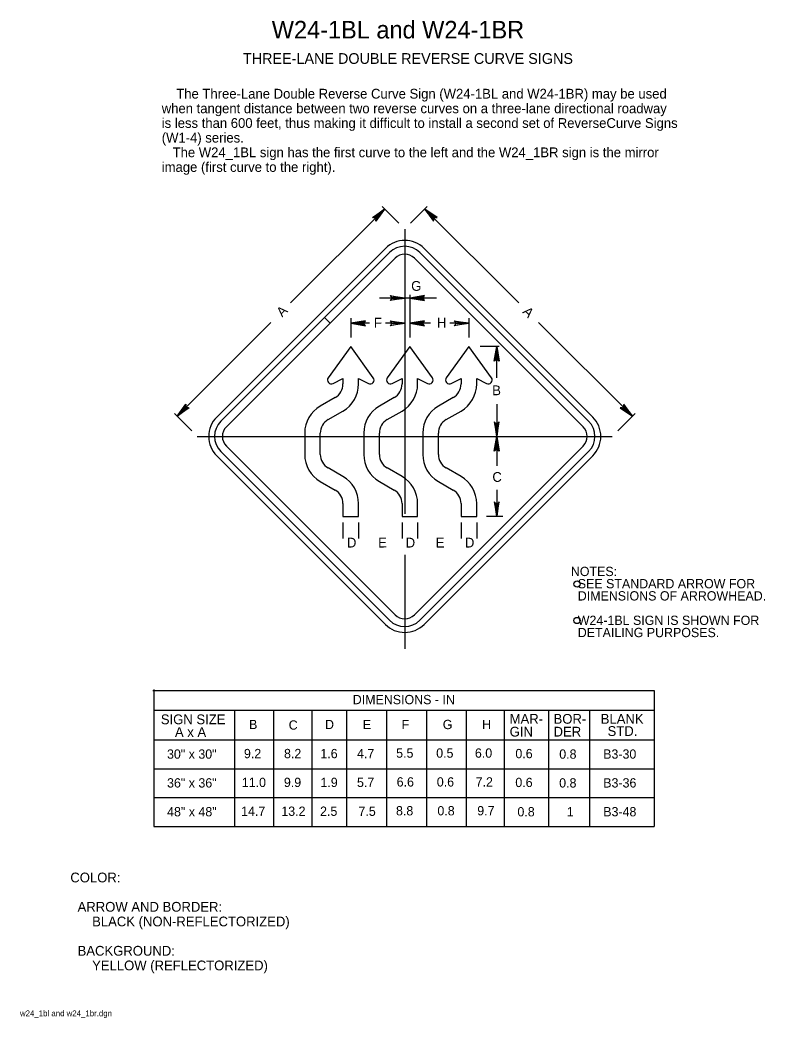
# Model space of a CAD drawing. Extents: x 0.013 to 0.203, y 0.004 to 0.259.
import ezdxf

# ---------------------------------------------------------------- set-up
doc = ezdxf.new("R2010")
doc.units = 0
for name, color, linetype in [('1', 7, 'Continuous'), ('2', 7, 'Continuous'), ('3', 7, 'Continuous')]:
    doc.layers.add(name, color=color, linetype=linetype)

# ---------------------------------------------------------------- blocks, each defined once
blk = doc.blocks.new('RARROW')
at = {"layer": '3'}
for p, q in [((-2.156, 0.28500000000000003), (-2.2665, 0.384625)), ((-2.2665, 0.384625), (0, 0)), ((0, 0), (-2.2665, -0.379125)), ((-2.156, 0.28500000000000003), (-2.075625, 0.12075)), ((0, 0), (-2.156, 0.28500000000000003)), ((-2.14975, -0.2705), (0, 0)), ((-2.075625, 0.12075), (0, 0)), ((0, 0), (-2.074, -0.108)), ((-2.2665, -0.379125), (-2.14975, -0.2705)), ((-2.074, -0.108), (-2.14975, -0.2705))]:
    blk.add_line(p, q, dxfattribs=at)

msp = doc.modelspace()

# ---------------------------------------------------------------- linework, layer by layer
at = {"layer": '1'}
for p, q in [((0.11101043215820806, 0.20572876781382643), (0.11101043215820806, 0.13292717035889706)), ((0.10606068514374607, 0.20078447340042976), (0.06292717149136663, 0.1576509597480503)), ((0.0905074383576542, 0.18310990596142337), (0.10712134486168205, 0.19972381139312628)), ((0.11489951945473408, 0.19972381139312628), (0.15803303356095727, 0.1565902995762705)), ((0.1590936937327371, 0.15765095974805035), (0.1159601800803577, 0.2007844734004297)), ((0.14141602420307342, 0.17532862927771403), (0.1159601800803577, 0.2007844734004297)), ((0.10853555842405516, 0.1983095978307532), (0.0919216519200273, 0.18169569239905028)), ((0.15661881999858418, 0.1551760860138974), (0.11348530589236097, 0.1983095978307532)), ((0.11231043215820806, 0.18893882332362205), (0.11231043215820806, 0.17803722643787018)), ((0.06398783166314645, 0.1565902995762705), (0.0905074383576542, 0.18310990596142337)), ((0.0919216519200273, 0.18169569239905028), (0.06540204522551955, 0.1551760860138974)), ((0.0905074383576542, 0.18310990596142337), (0.0919216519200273, 0.18169569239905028)), ((0.0919216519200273, 0.18169569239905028), (0.0905074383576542, 0.18310990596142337)), ((0.09721043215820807, 0.18292414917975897), (0.09721043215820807, 0.17803722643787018)), ((0.12741043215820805, 0.18292414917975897), (0.12741043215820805, 0.17803722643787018)), ((0.09721043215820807, 0.17570121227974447), (0.09144403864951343, 0.16770795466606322)), ((0.10297682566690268, 0.16770795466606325), (0.09721043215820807, 0.17570121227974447)), ((0.11231043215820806, 0.17570121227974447), (0.10654403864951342, 0.16770795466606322)), ((0.11807682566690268, 0.16770795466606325), (0.11231043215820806, 0.17570121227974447)), ((0.12741043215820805, 0.17570121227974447), (0.12164403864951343, 0.16770795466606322)), ((0.1331768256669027, 0.16770795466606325), (0.12741043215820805, 0.17570121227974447)), ((0.1345331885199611, 0.16766111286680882), (0.1345331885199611, 0.17570121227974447)), ((0.09270945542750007, 0.16623211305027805), (0.09521043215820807, 0.16750795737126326)), ((0.09521043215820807, 0.16750795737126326), (0.09521043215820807, 0.1661232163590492)), ((0.09921043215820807, 0.1661232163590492), (0.09921043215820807, 0.16750795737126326)), ((0.09921043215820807, 0.16750795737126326), (0.10171140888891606, 0.16623211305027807)), ((0.10780945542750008, 0.16623211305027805), (0.11031043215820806, 0.16750795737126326)), ((0.11031043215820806, 0.16750795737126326), (0.11031043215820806, 0.1661232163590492)), ((0.11431043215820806, 0.1661232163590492), (0.11431043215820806, 0.16750795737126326)), ((0.11431043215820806, 0.16750795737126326), (0.11681140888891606, 0.16623211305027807)), ((0.12290945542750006, 0.16623211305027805), (0.12541043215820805, 0.16750795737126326)), ((0.12541043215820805, 0.16750795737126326), (0.12541043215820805, 0.1661232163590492)), ((0.12941043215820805, 0.1661232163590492), (0.12941043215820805, 0.16750795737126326)), ((0.12941043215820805, 0.16750795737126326), (0.13191140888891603, 0.16623211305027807)), ((0.09321043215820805, 0.16265911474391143), (0.08942614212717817, 0.16047425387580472)), ((0.10831043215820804, 0.16265911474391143), (0.10452614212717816, 0.16047425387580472)), ((0.12341043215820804, 0.16265911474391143), (0.11962614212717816, 0.16047425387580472)), ((0.1345331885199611, 0.16097138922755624), (0.1345331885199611, 0.15270121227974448)), ((0.09142614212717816, 0.15701015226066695), (0.09521043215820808, 0.1591950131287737)), ((0.10652614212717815, 0.15701015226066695), (0.11031043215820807, 0.1591950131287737)), ((0.12162614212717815, 0.15701015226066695), (0.12541043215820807, 0.1591950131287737)), ((0.06229525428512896, 0.15700020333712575), (0.06229525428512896, 0.15700020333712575)), ((0.08542614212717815, 0.15354605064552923), (0.08542614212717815, 0.14809720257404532)), ((0.08942614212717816, 0.14809720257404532), (0.08942614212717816, 0.1535460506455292)), ((0.10052614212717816, 0.15354605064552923), (0.10052614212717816, 0.14809720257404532)), ((0.10452614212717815, 0.14809720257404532), (0.10452614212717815, 0.1535460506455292)), ((0.11562614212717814, 0.15354605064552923), (0.11562614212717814, 0.14809720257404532)), ((0.11962614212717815, 0.14809720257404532), (0.11962614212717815, 0.1535460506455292)), ((0.1345331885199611, 0.15270121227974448), (0.1345331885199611, 0.14514447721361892)), ((0.10712134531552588, 0.1056786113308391), (0.06398783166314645, 0.14881212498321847)), ((0.06540204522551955, 0.1502263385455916), (0.10853555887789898, 0.1070928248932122)), ((0.1134853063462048, 0.1070928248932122), (0.15661881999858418, 0.1502263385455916)), ((0.15803303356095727, 0.14881212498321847), (0.1148995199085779, 0.1056786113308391)), ((0.10606068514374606, 0.10461795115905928), (0.06292717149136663, 0.14775146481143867)), ((0.1590936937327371, 0.14775146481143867), (0.11596018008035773, 0.10461795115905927)), ((0.09521043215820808, 0.14244824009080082), (0.09142614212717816, 0.1446331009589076)), ((0.11031043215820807, 0.14244824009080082), (0.10652614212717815, 0.1446331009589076)), ((0.12541043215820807, 0.14244824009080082), (0.12162614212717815, 0.1446331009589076)), ((0.08942614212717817, 0.14116899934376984), (0.09321043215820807, 0.1389841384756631)), ((0.10452614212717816, 0.14116899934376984), (0.10831043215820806, 0.1389841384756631)), ((0.11962614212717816, 0.14116899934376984), (0.12341043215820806, 0.1389841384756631)), ((0.1345331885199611, 0.13903582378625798), (0.1345331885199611, 0.1322012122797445)), ((0.09521043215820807, 0.13552003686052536), (0.09521043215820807, 0.1322012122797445)), ((0.09921043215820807, 0.1322012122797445), (0.09921043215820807, 0.13552003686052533)), ((0.11031043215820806, 0.13552003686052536), (0.11031043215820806, 0.1322012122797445)), ((0.11431043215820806, 0.1322012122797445), (0.11431043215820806, 0.13552003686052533)), ((0.12541043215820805, 0.13552003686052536), (0.12541043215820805, 0.1322012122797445)), ((0.12941043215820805, 0.1322012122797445), (0.12941043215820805, 0.13552003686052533)), ((0.09521043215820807, 0.1322012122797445), (0.09921043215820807, 0.1322012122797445)), ((0.09521043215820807, 0.13067166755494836), (0.09521043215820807, 0.12663055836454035)), ((0.09921043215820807, 0.13067166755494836), (0.09921043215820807, 0.12663055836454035)), ((0.11031043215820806, 0.1322012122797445), (0.11431043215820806, 0.1322012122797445)), ((0.11031043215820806, 0.13067166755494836), (0.11031043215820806, 0.12663055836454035)), ((0.11431043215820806, 0.13067166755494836), (0.11431043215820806, 0.12663055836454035)), ((0.12541043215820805, 0.1322012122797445), (0.12941043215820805, 0.1322012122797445)), ((0.12541043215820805, 0.13067166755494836), (0.12541043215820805, 0.12663055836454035)), ((0.12941043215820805, 0.13067166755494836), (0.12941043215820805, 0.12663055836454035)), ((0.11101043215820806, 0.12240149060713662), (0.11101043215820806, 0.09840505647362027))]:
    msp.add_line(p, q, dxfattribs=at)
for centre in [(0.1550658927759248, 0.11496502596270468), (0.1550658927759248, 0.10561564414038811)]:
    msp.add_circle(centre, 0.0008079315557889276, dxfattribs=at)
for centre, radius, start, end in [((0.11101043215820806, 0.19583472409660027), 0.007, 45, 135), ((0.11101043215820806, 0.19583472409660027), 0.005500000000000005, 45, 135), ((0.11101043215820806, 0.19583472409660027), 0.003499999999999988, 45, 135), ((0.09225503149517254, 0.1671228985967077), 0.001, 144.1930488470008, 297.02787514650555), ((0.09121043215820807, 0.1661232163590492), 0.004, 299.9999999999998, 6.394884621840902e-14), ((0.09121043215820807, 0.1661232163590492), 0.008, 300.0000000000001, 359.99999999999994), ((0.10216583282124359, 0.1671228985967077), 0.001, 242.9721248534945, 35.80695115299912), ((0.10735503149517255, 0.1671228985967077), 0.001, 144.1930488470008, 297.02787514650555), ((0.10631043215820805, 0.1661232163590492), 0.004, 299.9999999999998, 6.394884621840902e-14), ((0.10631043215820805, 0.1661232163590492), 0.008, 300.0000000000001, 359.99999999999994), ((0.11726583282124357, 0.1671228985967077), 0.001, 242.9721248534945, 35.80695115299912), ((0.12245503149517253, 0.1671228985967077), 0.001, 144.1930488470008, 297.02787514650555), ((0.12141043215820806, 0.1661232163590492), 0.004, 299.9999999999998, 6.394884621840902e-14), ((0.12141043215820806, 0.1661232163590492), 0.008, 300.0000000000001, 359.99999999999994), ((0.13236583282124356, 0.1671228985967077), 0.001, 242.9721248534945, 35.80695115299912), ((0.09342614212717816, 0.15354605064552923), 0.008, 119.99999999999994, 180.0000000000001), ((0.10852614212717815, 0.15354605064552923), 0.008, 119.99999999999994, 180.0000000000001), ((0.12362614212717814, 0.15354605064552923), 0.008, 119.99999999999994, 180.0000000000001), ((0.06787691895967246, 0.15270121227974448), 0.007, 135.00000000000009, 225.00000000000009), ((0.06787691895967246, 0.15270121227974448), 0.005500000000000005, 135, 225), ((0.09342614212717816, 0.1535460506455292), 0.004, 119.99999999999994, 180), ((0.10852614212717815, 0.1535460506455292), 0.004, 119.99999999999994, 180), ((0.12362614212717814, 0.1535460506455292), 0.004, 119.99999999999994, 180), ((0.15414394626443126, 0.15270121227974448), 0.005500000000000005, 315, 45), ((0.15414394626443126, 0.15270121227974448), 0.006999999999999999, 315, 45.0000000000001), ((0.06787691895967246, 0.15270121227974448), 0.003499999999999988, 135, 225), ((0.15414394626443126, 0.15270121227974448), 0.003499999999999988, 315, 45), ((0.09342614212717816, 0.14809720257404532), 0.008, 180, 240.00000000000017), ((0.09342614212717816, 0.14809720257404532), 0.004, 179.9999999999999, 239.9999999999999), ((0.10852614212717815, 0.14809720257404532), 0.008, 180, 240.00000000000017), ((0.10852614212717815, 0.14809720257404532), 0.004, 179.9999999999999, 239.9999999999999), ((0.12362614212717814, 0.14809720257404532), 0.008, 180, 240.00000000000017), ((0.12362614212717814, 0.14809720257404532), 0.004, 179.9999999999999, 239.9999999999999), ((0.09121043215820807, 0.13552003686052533), 0.008, 359.99999999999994, 59.99999999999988), ((0.10631043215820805, 0.13552003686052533), 0.008, 359.99999999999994, 59.99999999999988), ((0.12141043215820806, 0.13552003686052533), 0.008, 359.99999999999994, 59.99999999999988), ((0.09121043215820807, 0.13552003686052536), 0.004, 360, 59.999999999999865), ((0.10631043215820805, 0.13552003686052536), 0.004, 360, 59.999999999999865), ((0.12141043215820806, 0.13552003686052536), 0.004, 360, 59.999999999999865), ((0.11101043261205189, 0.10956769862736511), 0.005500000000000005, 225, 315), ((0.11101043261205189, 0.10956769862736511), 0.003499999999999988, 225, 315), ((0.11101043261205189, 0.10956769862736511), 0.006999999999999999, 224.99999999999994, 315)]:
    msp.add_arc(centre, radius, start, end, dxfattribs=at)
at = {"layer": '3'}
for p, q in [((0.10584291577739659, 0.21088090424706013), (0.08181634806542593, 0.18685433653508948)), ((0.10949715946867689, 0.2072341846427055), (0.10523411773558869, 0.21148844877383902)), ((0.11252370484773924, 0.2072341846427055), (0.11678674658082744, 0.21148844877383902)), ((0.11617794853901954, 0.21088090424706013), (0.1402045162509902, 0.18685433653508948)), ((0.11101043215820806, 0.1880930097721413), (0.10453030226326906, 0.1880930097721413)), ((0.11231043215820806, 0.1880930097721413), (0.11101043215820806, 0.1880930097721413)), ((0.1190970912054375, 0.1880930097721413), (0.11231043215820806, 0.1880930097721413)), ((0.07678554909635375, 0.18182353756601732), (0.05280990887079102, 0.15784789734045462)), ((0.10196936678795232, 0.18164240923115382), (0.09721043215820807, 0.18164240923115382)), ((0.11101043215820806, 0.18164240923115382), (0.10610445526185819, 0.18164240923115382)), ((0.11756992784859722, 0.18164240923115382), (0.11231043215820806, 0.18164240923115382)), ((0.12741043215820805, 0.18164240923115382), (0.12255082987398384, 0.18164240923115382)), ((0.1452353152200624, 0.18182353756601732), (0.16921095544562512, 0.15784789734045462)), ((0.13514405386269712, 0.17570121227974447), (0.13030412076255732, 0.17570121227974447)), ((0.05654316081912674, 0.1541223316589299), (0.052096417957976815, 0.15855991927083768)), ((0.16547770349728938, 0.1541223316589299), (0.1699244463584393, 0.15855991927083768)), ((0.05795792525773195, 0.15270121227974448), (0.16408382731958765, 0.15270121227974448)), ((0.13608384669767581, 0.1322012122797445), (0.131901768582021, 0.1322012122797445)), ((0.046598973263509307, 0.0877038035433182), (0.17475379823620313, 0.0877038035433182)), ((0.046834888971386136, 0.08796253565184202), (0.046834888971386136, 0.052953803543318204)), ((0.1747537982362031, 0.08257775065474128), (0.046834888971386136, 0.08257775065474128)), ((0.06745767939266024, 0.08257775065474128), (0.06745767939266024, 0.052953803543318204)), ((0.08729194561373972, 0.08257775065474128), (0.08729194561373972, 0.052953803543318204)), ((0.14773871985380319, 0.08257775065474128), (0.14773871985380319, 0.052953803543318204)), ((0.15826439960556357, 0.08257775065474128), (0.15826439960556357, 0.052953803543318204)), ((0.046834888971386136, 0.07507880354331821), (0.1747537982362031, 0.07507880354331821)), ((0.04684897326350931, 0.0677038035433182), (0.1747537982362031, 0.0677038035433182)), ((0.046863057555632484, 0.0603288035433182), (0.1747537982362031, 0.0603288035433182)), ((0.046834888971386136, 0.052953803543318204), (0.1747537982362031, 0.052953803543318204))]:
    msp.add_line(p, q, dxfattribs=at)
for points in [[(0.1747537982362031, 0.0877038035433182), (0.1747537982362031, 0.052953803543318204)], [(0.07748488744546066, 0.08257775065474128), (0.07748488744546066, 0.052953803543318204)], [(0.09615218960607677, 0.08257775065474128), (0.09615218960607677, 0.052953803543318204)], [(0.10634489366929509, 0.08257775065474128), (0.10634489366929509, 0.052953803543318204)], [(0.1165375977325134, 0.08257775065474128), (0.1165375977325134, 0.052953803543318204)], [(0.12673030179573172, 0.08257775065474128), (0.12673030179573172, 0.052953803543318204)], [(0.13646120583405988, 0.08257775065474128), (0.13646120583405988, 0.052953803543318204)]]:
    msp.add_lwpolyline(points, dxfattribs=at)

# ---------------------------------------------------------------- block references
for p, xscale, yscale, rotation in [((0.10584291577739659, 0.21088090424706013), 0.0016545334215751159, 0.0016366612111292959, 44.91708286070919), ((0.11617794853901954, 0.21088090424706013), 0.0016545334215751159, -0.0016366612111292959, 135.08291713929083), ((0.11101043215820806, 0.1880930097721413), 0.0016545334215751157, 0.001636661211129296, -0.08291713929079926), ((0.11231043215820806, 0.1880930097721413), 0.0016545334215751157, -0.001636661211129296, -179.9170828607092), ((0.09721043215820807, 0.18164240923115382), 0.0016545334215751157, -0.001636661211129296, -179.9170828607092), ((0.11101043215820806, 0.18164240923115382), 0.0016545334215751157, 0.001636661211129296, -0.08291713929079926), ((0.11231043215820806, 0.18164240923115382), 0.0016545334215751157, -0.001636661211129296, -179.9170828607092), ((0.12741043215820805, 0.18164240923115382), 0.0016545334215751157, 0.001636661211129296, -0.08291713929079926), ((0.1345331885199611, 0.17570121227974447), 0.0016545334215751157, 0.001636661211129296, 89.9170828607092), ((0.05280990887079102, 0.15784789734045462), 0.001654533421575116, 0.001636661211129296, -135.0829171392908), ((0.16921095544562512, 0.15784789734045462), 0.001654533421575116, -0.001636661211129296, -44.917082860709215), ((0.1345331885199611, 0.15270121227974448), 0.0016545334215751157, -0.001636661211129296, -89.9170828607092), ((0.1345331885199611, 0.15270121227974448), 0.0016545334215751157, 0.001636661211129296, 89.9170828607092), ((0.1345331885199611, 0.1322012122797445), 0.0016545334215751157, -0.001636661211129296, -89.9170828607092)]:
    msp.add_blockref('RARROW', p, dxfattribs=dict(at, xscale=xscale, yscale=yscale, rotation=rotation))

# ---------------------------------------------------------------- texts
at = {"layer": '1'}
for s, height, p in [('W24-1BL and W24-1BR', 0.0045000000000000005, (0.07700454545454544, 0.2545)), ('THREE-LANE DOUBLE REVERSE CURVE SIGNS', 0.00275025, (0.06962496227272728, 0.248)), ('COLOR:', 0.0024997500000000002, (0.025500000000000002, 0.038624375)), ('  ARROW AND BORDER:', 0.0024997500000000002, (0.025500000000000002, 0.031124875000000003)), ('      BLACK (NON-REFLECTORIZED)', 0.0024997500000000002, (0.025500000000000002, 0.027375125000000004)), ('  BACKGROUND:', 0.0024997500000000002, (0.025500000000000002, 0.019875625)), ('      YELLOW (REFLECTORIZED)', 0.0024997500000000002, (0.025500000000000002, 0.016125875)), ('w24_1bl and w24_1br.dgn', 0.0015, (0.012625, 0.004375))]:
    msp.add_text(s, height=height, dxfattribs=at).set_placement(p)
at = {"layer": '2'}
for s, p in [('    The Three-Lane Double Reverse Curve Sign (W24-1BL and W24-1BR) may be used', (0.048875, 0.23912525)), ('when tangent distance between two reverse curves on a three-lane directional roadway', (0.048875, 0.2353755)), ('is less than 600 feet, thus making it difficult to install a second set of ReverseCurve Signs ', (0.048875, 0.23162575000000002)), ('(W1-4) series.', (0.048875, 0.22787600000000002)), ('   The W24_1BL sign has the first curve to the left and the W24_1BR sign is the mirror', (0.048875, 0.22412625)), ('image (first curve to the right).', (0.048875, 0.2203765))]:
    msp.add_text(s, height=0.0024997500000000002, dxfattribs=at).set_placement(p)
at = {"layer": '3'}
for s, height, rotation, p in [('G', 0.002499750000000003, 0.08291666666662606, (0.11266077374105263, 0.18994904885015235)), ('A', 0.00249975, 44.91708333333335, (0.07969460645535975, 0.18307431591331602)), ('A', 0.00249975, 315.0829166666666, (0.14097236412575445, 0.1844242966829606)), ('F', 0.002499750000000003, 0.08291666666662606, (0.1031172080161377, 0.18055145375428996)), ('H', 0.002499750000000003, 359.9170833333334, (0.11922796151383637, 0.1805539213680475)), ('B', 0.002499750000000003, 359.9170833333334, (0.1333727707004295, 0.16324974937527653)), ('C', 0.002499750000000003, 0.08291666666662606, (0.13342486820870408, 0.1410798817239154)), ('D', 0.002499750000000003, 359.9170833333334, (0.0962302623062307, 0.12429102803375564)), ('E', 0.002499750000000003, 0.08291666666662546, (0.10420033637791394, 0.12428846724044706)), ('D', 0.002499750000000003, 0.08291666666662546, (0.11126332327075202, 0.12428808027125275)), ('E', 0.002499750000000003, 359.9170833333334, (0.11892625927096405, 0.12429102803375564)), ('D', 0.002499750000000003, 359.9170833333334, (0.12639761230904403, 0.12429102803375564)), ('DIMENSIONS - IN', 0.0023752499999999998, 360, (0.09771867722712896, 0.08420380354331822)), ('4.7', 0.0023752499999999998, 360, (0.0988103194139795, 0.07039117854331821)), ('5.5', 0.0023752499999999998, 360, (0.1088172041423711, 0.07051617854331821)), ('6.0', 0.0023752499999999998, 360, (0.12895379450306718, 0.07051617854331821)), ('0.6', 0.0023752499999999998, 360, (0.13930116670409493, 0.07038595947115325)), ('0.8', 0.0023752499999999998, 360, (0.15051831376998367, 0.07026095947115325)), ('5.7', 0.0023752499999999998, 360, (0.09879623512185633, 0.0630161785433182)), ('6.6', 0.0023752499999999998, 360, (0.10894621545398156, 0.0631411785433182)), ('7.2', 0.0023752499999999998, 360, (0.1291421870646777, 0.0631411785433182)), ('0.6', 0.0023752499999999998, 360, (0.13928708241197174, 0.06301095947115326)), ('0.8', 0.0023752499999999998, 360, (0.1505042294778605, 0.06288595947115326)), ('2.5', 0.0023752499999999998, 360, (0.08935894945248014, 0.0556411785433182)), ('7.5', 0.0023752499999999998, 360, (0.09918732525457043, 0.0556411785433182)), ('8.8', 0.0023752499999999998, 360, (0.10877320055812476, 0.0557661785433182)), ('9.7', 0.0023752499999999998, 360, (0.1295501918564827, 0.0557661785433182)), ('1', 0.0023752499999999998, 360, (0.15244548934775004, 0.05551095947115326))]:
    msp.add_text(s, height=height, rotation=rotation, dxfattribs=at).set_placement(p)
for s, height, p in [('NOTES:', 0.0023752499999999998, (0.15348758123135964, 0.11698193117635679)), ('  SEE STANDARD ARROW FOR', 0.0023752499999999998, (0.15348758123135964, 0.11385668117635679)), ('  DIMENSIONS OF ARROWHEAD.', 0.0023752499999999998, (0.15348758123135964, 0.11073143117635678)), ('  W24-1BL SIGN IS SHOWN FOR', 0.0023752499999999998, (0.15348758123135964, 0.10448093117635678)), ('  DETAILING PURPOSES.', 0.0023752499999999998, (0.15348758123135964, 0.10135568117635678)), ('MAR-', 0.0024997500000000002, (0.13783900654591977, 0.07920405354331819)), ('BOR-', 0.0024997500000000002, (0.14906803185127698, 0.07920405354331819)), ('BLANK', 0.0024997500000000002, (0.16112925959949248, 0.0792038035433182)), ('SIGN SIZE', 0.0024997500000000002, (0.04863537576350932, 0.0790788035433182)), ('B', 0.0023752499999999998, (0.07120094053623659, 0.0778288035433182)), ('C', 0.0023752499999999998, (0.08134002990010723, 0.07769858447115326)), ('D', 0.0023752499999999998, (0.09061949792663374, 0.0778288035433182)), ('E', 0.0023752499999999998, (0.10028268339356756, 0.0778288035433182)), ('F', 0.0023752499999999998, (0.110206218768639, 0.0778288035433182)), ('G', 0.0023752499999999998, (0.120735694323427, 0.0778288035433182)), ('H', 0.0023752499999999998, (0.13078383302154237, 0.0778288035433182)), ('A x A', 0.0024997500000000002, (0.052247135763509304, 0.0758290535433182)), ('GIN', 0.0024997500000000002, (0.13783900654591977, 0.0759271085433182)), ('DER', 0.0024997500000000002, (0.14906803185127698, 0.0759271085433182)), ('STD.', 0.0024997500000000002, (0.16287925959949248, 0.0760788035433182)), ('30" x 30"', 0.0023752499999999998, (0.05021938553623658, 0.07026617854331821)), ('9.2', 0.0023752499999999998, (0.06989394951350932, 0.07039117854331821)), ('8.2', 0.0023752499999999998, (0.08014394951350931, 0.07039117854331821)), ('1.6', 0.0023752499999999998, (0.08943419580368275, 0.07039117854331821)), ('0.5', 0.0023752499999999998, (0.11905515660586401, 0.07051617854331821)), ('B3-30', 0.0023752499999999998, (0.16175064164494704, 0.07026617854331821)), ('36" x 36"', 0.0023752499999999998, (0.05023346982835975, 0.0628911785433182)), ('11.0', 0.0023752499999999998, (0.06934769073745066, 0.0630161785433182)), ('9.9', 0.0023752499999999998, (0.08011016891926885, 0.0630161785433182)), ('1.9', 0.0023752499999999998, (0.08945187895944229, 0.0630161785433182)), ('0.6', 0.0023752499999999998, (0.11921233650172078, 0.0631411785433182)), ('B3-36', 0.0023752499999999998, (0.16176976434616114, 0.0628911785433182)), ('48" x 48"', 0.0023752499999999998, (0.05024755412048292, 0.05551617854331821)), ('14.7', 0.0023752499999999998, (0.06918651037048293, 0.0556411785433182)), ('13.2', 0.0023752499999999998, (0.07945234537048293, 0.0556411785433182)), ('0.8', 0.0023752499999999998, (0.11935943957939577, 0.0557661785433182)), ('0.8', 0.0023752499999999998, (0.13982771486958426, 0.05551095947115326)), ('B3-48', 0.0023752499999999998, (0.1617708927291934, 0.05551617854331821))]:
    msp.add_text(s, height=height, dxfattribs=at).set_placement(p)

doc.saveas('drawing.dxf')
